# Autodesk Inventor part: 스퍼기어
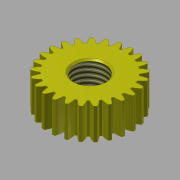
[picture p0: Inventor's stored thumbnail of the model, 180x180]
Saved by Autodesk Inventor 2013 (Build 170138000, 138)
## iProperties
Created: 2017-04
Part Number: 스퍼기어
Material: 강철
Document SubType Name: Modeling
Designer: mduedu
Categories: <?xml version="1.0" encoding="UTF-16"?> <MemberInstance><Categories><FamilyTemplate><FamilyTemplateParameter ValueType="xs:double" Id="1" ObjectReferenceKey="da
Density: 7.85 g/cm^3
Mass: 32.0047 g
Surface Area: 26.9526 cm^2
Volume: 4.07703 cm^3
CustomPartVersion: 1
Author: mduedu
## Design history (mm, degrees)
sketch "Sketch1"
  geometry: C1 r 13.5 at (0, 0)
  constraints: 1 centre point
  dimensions: "d0" = 27 diameter of C1 (= da_da)
extrude "Extrusion1" new body sketch "Sketch1" distance "d1" = 10 (= da_b); taper "d2" = 0 deg
workplane "Work Plane2"
sketch "Sketch2"
  geometry: C1 r 13.5 at (0, 0) reference; C2 r 12.5 at (0, 0)
  constraints: 1 centre point, 1 coincident
  dimensions: "d3" = 25 diameter of C2 (= da_dw)
feature "피치 지름" sketch "Sketch2" dims "d4" = 10, "d5" = 0
workplane "Work Plane8"
workplane "Work Plane9"
feature "스퍼 기어" dims "da_b" = 10, "da_d" = 25, "da_aw" = 25, "da_da" = 27, "da_df" = 22.5, "da_dw" = 25, angle "da_beta" = 0 deg, "da_lefttooth" = 0, "da_righttooth" = 0
sketch "스케치3"
  geometry: C1 r 5 at (0, 0); 1 further point
  constraints: 1 centre point, 1 coincident
  dimensions: "d49" = 10 diameter of C1
extrude "돌출2" cut sketch "스케치3" stored distance "d50" = 10; taper "d51" = 0 deg
feature "스레드1" dims "d52" = 10, "d53" = 0
chamfer "모따기1" distance "d54" = 0.5; stored, may be unused: second distance "d55" = 2, angle "d56" = 45 deg
body "Solid1"
body "Srf1"
other parameters: "d16" = 25 (= da_aw), "d17" = 0, "d34" = 1.25664 (computed from da_z), "d39" = 0, "d41" = 0, "d43" = 25 (= da_aw), "d46" = 25 (= da_aw), "d47" = 0, "d48" = 0
